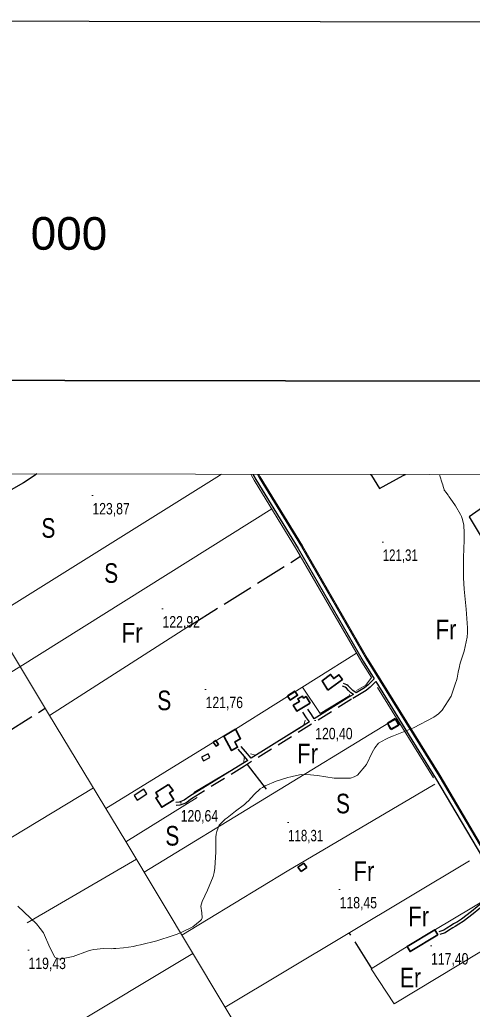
# Model space of a CAD drawing. Extents: x 487425 to 492029, y 4383576 to 4386788.
# Drawn here: x 488084 to 488430, y 4386031 to 4386788 of the extents above; entities that cross this region are included whole.
import ezdxf
from ezdxf.enums import TextEntityAlignment as Align

# ---------------------------------------------------------------- set-up
doc = ezdxf.new("R2010")
doc.units = 0
doc.header["$LTSCALE"] = 4
for name, pattern in [('DOTTED', [1.5, 0.3, -1.2]), ('LONG_DASHED', [7.5, 6, -1.5]), ('MEDIUM_DASHED', [4.5, 3, -1.5])]:
    doc.linetypes.add(name, pattern=pattern)
for name, color, linetype, lineweight in [('1', 7, 'Continuous', 13), ('2', 7, 'DOTTED', 13), ('21', 7, 'Continuous', 25), ('25', 7, 'LONG_DASHED', 25), ('38', 7, 'Continuous', 25), ('47', 7, 'Continuous', 35), ('48', 7, 'MEDIUM_DASHED', 25), ('49', 7, 'LONG_DASHED', 35), ('51', 7, 'Continuous', 13), ('7', 7, 'Continuous', 13), ('8', 7, 'Continuous', 25), ('9', 7, 'Continuous', 13)]:
    doc.layers.add(name, color=color, linetype=linetype, lineweight=lineweight)
doc.layers.add('31', color=7, linetype='Continuous')

msp = doc.modelspace()

# ---------------------------------------------------------------- linework, layer by layer
at = {"layer": '1', "lineweight": 25}
msp.add_lwpolyline([(487429.26, 4386787.97), (492029.26, 4386781.28), (492024.61, 4383576.28), (487424.61, 4383582.97)], close=True, dxfattribs=at)
at = {"layer": '1', "lineweight": 35}
msp.add_lwpolyline([(487611.46, 4386512.7), (491328.86, 4386507.3), (491325.3, 4384052.3), (487607.9, 4384057.7)], close=True, dxfattribs=at)
at = {"layer": '1'}
msp.add_lwpolyline([(487681.9, 4386441.2), (491258.2, 4386436), (491255.4, 4384123.8), (487678, 4384129)], close=True, dxfattribs=at)
at = {"layer": '21'}
for points in [[(488224.69, 4386221.07), (488229.62, 4386223.59), (488228.13, 4386226.51), (488223.2, 4386223.99)], [(488179.06, 4386199.54), (488171.66, 4386194.75), (488174.01, 4386191.12), (488181.41, 4386195.91)]]:
    msp.add_lwpolyline(points, close=True, dxfattribs=at)
at = {"layer": '25'}
for p, q in [((488352.62, 4386440.22), (488353.21, 4386439.31)), ((488377.66, 4386439.27), (488379.37, 4386440.19)), ((488215.18, 4386325.09), (488299, 4386377.62)), ((488257.98, 4386218.31), (488276.07, 4386195)), ((488353.54, 4386062.4), (488336.27, 4386089.61))]:
    msp.add_line(p, q, dxfattribs=at)
for points in [[(488353.21, 4386439.31), (488359.47, 4386429.53), (488377.66, 4386439.27)], [(488468.34, 4386435.15), (488427.95, 4386407.89), (488537.35, 4386226.21)], [(487959.27, 4386169.33), (487996.84, 4386194.26), (488103.35, 4386261.37)]]:
    msp.add_lwpolyline(points, dxfattribs=at)
at = {"layer": '38'}
for p, q in [((488262.43, 4386440.36), (488262.96, 4386439.44)), ((488265.95, 4386440.35), (488266.47, 4386439.44)), ((488305.7, 4386250.92), (488261.21, 4386223.13))]:
    msp.add_line(p, q, dxfattribs=at)
for points in [[(488262.96, 4386439.44), (488264.69, 4386436.44), (488297.09, 4386383.48), (488346.91, 4386297.31), (488355.27, 4386283.84)], [(488266.47, 4386439.44), (488267.3, 4386437.99), (488299.7, 4386385.03), (488349.51, 4386298.86), (488404.98, 4386209.41), (488439.82, 4386150.66)], [(488341.62, 4386273.2), (488338.88, 4386274.89), (488337.32, 4386276.62), (488335.55, 4386278.44), (488334.3, 4386279.37), (488331.97, 4386280.42)], [(488355.27, 4386283.84), (488350.65, 4386279.18), (488347.88, 4386276.91), (488341.62, 4386273.2)], [(488356.55, 4386281.75), (488402.39, 4386207.84), (488453.88, 4386121.01)], [(488339.39, 4386271.89), (488336.63, 4386270.25), (488309.43, 4386253.26)], [(488305.7, 4386250.92), (488303.56, 4386254.08), (488300.82, 4386258.33)], [(488261.21, 4386223.13), (488256.95, 4386228.17), (488253.45, 4386232.12)], [(488258.59, 4386221.5), (488254.78, 4386219.11), (488214.1, 4386194.12), (488209.88, 4386190.94), (488206.12, 4386189.52), (488203.42, 4386189.27)], [(488453.88, 4386121.01), (488448.21, 4386118.36), (488438.52, 4386113.1), (488429.84, 4386105.88), (488422.24, 4386099.99), (488419.03, 4386098.03), (488416.16, 4386096.34), (488414.35, 4386095.24), (488411.01, 4386093.24), (488408.74, 4386091.66), (488404.86, 4386090.4)]]:
    msp.add_lwpolyline(points, dxfattribs=at)
at = {"layer": '38', "linetype": 'MEDIUM_DASHED'}
for points in [[(488356.55, 4386281.75), (488352.25, 4386277.42), (488349.26, 4386274.95), (488337.87, 4386268.21), (488256.04, 4386217.09), (488215.44, 4386192.14), (488211.04, 4386188.83), (488206.66, 4386187.18), (488203.64, 4386186.89)], [(488339.39, 4386271.89), (488337.4, 4386273.11), (488335.65, 4386275.06), (488334.04, 4386276.71), (488333.13, 4386277.39), (488331.03, 4386278.33)], [(488309.43, 4386253.26), (488307.23, 4386256.51), (488304.51, 4386260.71)], [(488258.59, 4386221.5), (488254.64, 4386226.17), (488251.16, 4386230.09)], [(488455.03, 4386119.07), (488449.22, 4386116.35), (488439.79, 4386111.23), (488431.25, 4386104.12), (488423.52, 4386098.14), (488420.19, 4386096.1), (488417.32, 4386094.41), (488415.51, 4386093.31), (488412.23, 4386091.34), (488409.75, 4386089.62), (488405.56, 4386088.26)]]:
    msp.add_lwpolyline(points, dxfattribs=at)
at = {"layer": '47'}
for points in [[(488319.98, 4386275.28), (488331.03, 4386283.48), (488328.39, 4386287.03), (488324.34, 4386284.03), (488321.98, 4386287.2), (488315.45, 4386282.34)], [(488288.95, 4386270.76), (488294.59, 4386274.49), (488296.68, 4386271.34), (488291.04, 4386267.61)], [(488306.37, 4386265.31), (488296.02, 4386259.2), (488293.39, 4386263.65), (488298.13, 4386266.45), (488296.85, 4386268.6), (488300.37, 4386270.69), (488301.27, 4386269.16), (488303.27, 4386270.35)], [(488240.14, 4386240.1), (488246.16, 4386229.01), (488250.82, 4386231.55), (488248.59, 4386235.62), (488253.02, 4386238.05), (488249.07, 4386245.24)], [(488232.2, 4386235.39), (488234.37, 4386232.36), (488236.24, 4386233.7), (488234.07, 4386236.73)], [(488198, 4386203.15), (488188.1, 4386196.88), (488189.97, 4386193.91), (488188.15, 4386192.76), (488192.67, 4386185.59), (488201.86, 4386191.39), (488198.57, 4386196.58), (488201.34, 4386198.35)], [(488380.55, 4386079.09), (488401.74, 4386091.88), (488404.05, 4386088.05), (488382.86, 4386075.26)]]:
    msp.add_lwpolyline(points, close=True, dxfattribs=at)
at = {"layer": '48'}
msp.add_lwpolyline([(488365.61, 4386249.7), (488372.39, 4386253.28), (488374.68, 4386248.93), (488367.9, 4386245.35)], close=True, dxfattribs=at)
at = {"layer": '49'}
for points in [[(488365.46, 4386249.93), (488371.42, 4386253.4), (488374.29, 4386248.48), (488368.33, 4386245.01)], [(488303.73, 4386139.45), (488299.34, 4386136.39), (488296.99, 4386139.75), (488301.38, 4386142.81)]]:
    msp.add_lwpolyline(points, close=True, dxfattribs=at)
at = {"layer": '51'}
for p, q in [((488066.84, 4386333.15), (488236.98, 4386439.48)), ((488236.98, 4386439.48), (488238.44, 4386440.39)), ((488260.97, 4386440.36), (488261.49, 4386439.45)), ((488267.01, 4386440.35), (488267.53, 4386439.44)), ((488106.67, 4386255.89), (488215.52, 4386325.31)), ((488249.07, 4386245.24), (488341.86, 4386303.49)), ((488357.86, 4386277.23), (488400.78, 4386208.01)), ((488179.28, 4386135.96), (488366.63, 4386250.24)), ((488149.84, 4386184.74), (488240.22, 4386240.15)), ((488140.34, 4386200.41), (487948.07, 4386084.44)), ((488165.31, 4386159.25), (488219.72, 4386193.22)), ((488173.29, 4386145.95), (488089.59, 4386097.17)), ((488241.28, 4386032.7), (488428.26, 4386144.71)), ((488445.81, 4386118.1), (488401.07, 4386091.47)), ((488216.53, 4386073.86), (488008.28, 4385949.02))]:
    msp.add_line(p, q, dxfattribs=at)
for points in [[(488261.49, 4386439.45), (488263.59, 4386435.79), (488295.99, 4386382.82), (488345.81, 4386296.64), (488353.17, 4386284.79)], [(488267.53, 4386439.44), (488268.09, 4386438.46), (488300.49, 4386385.5), (488350.29, 4386299.34), (488405.77, 4386209.89), (488439.12, 4386153.67)], [(488276.91, 4386414.02), (488084.14, 4386293.16), (487939.73, 4386205.49), (487959.27, 4386169.33)], [(488065.17, 4386324.54), (488105.89, 4386257.16), (488165.17, 4386159.48), (488216.27, 4386074.28), (488260.52, 4386000.7), (488321.21, 4385902.03)], [(488341.89, 4386275.03), (488348.98, 4386279), (488353.17, 4386284.79)], [(488300.57, 4386277.57), (488314.08, 4386257.27), (488336.74, 4386271.11), (488336.45, 4386271.94)], [(488260.69, 4386226.59), (488264.58, 4386225.57), (488300.61, 4386247.67), (488301.45, 4386248.71), (488301.99, 4386250.2), (488302.54, 4386252.15)], [(488217.29, 4386196.85), (488255.43, 4386219.6), (488255.93, 4386223.72)], [(488401.84, 4386203.3), (488288.78, 4386136.85), (488208.12, 4386087.87)], [(488380.55, 4386079.09), (488353.12, 4386062.14), (488370.52, 4386035.39), (488468.26, 4386094.08)]]:
    msp.add_lwpolyline(points, dxfattribs=at)
at = {"layer": '7'}
for p, q in [((488139.1, 4386424), (488140.1, 4386424)), ((488361.36, 4386388.46), (488362.36, 4386388.46)), ((488192.8, 4386337.49), (488193.8, 4386337.49)), ((488225.79, 4386275.82), (488226.79, 4386275.82)), ((488309.69, 4386251.99), (488310.69, 4386251.99)), ((488206.72, 4386189.09), (488207.72, 4386189.09)), ((488289, 4386173.97), (488290, 4386173.97)), ((488328.4, 4386122.66), (488329.4, 4386122.66)), ((488090.2, 4386076.23), (488091.2, 4386076.23)), ((488398.36, 4386079.7), (488399.36, 4386079.7))]:
    msp.add_line(p, q, dxfattribs=at)
at = {"layer": '8'}
msp.add_line((488097.04, 4386440.6), (488095.68, 4386439.69), dxfattribs=at)
msp.add_lwpolyline([(488095.68, 4386439.69), (488086.98, 4386433.88), (488068.27, 4386423.32), (488063.87, 4386421.53), (488059.81, 4386420.22), (488047.97, 4386419.6), (488040.04, 4386422.79), (488038.44, 4386423.88), (488037.1, 4386425.08), (488034.42, 4386430.16), (488033.19, 4386435.13), (488032.76, 4386436.26), (488032.3, 4386437.27), (488030.47, 4386439.79)], dxfattribs=at)
at = {"layer": '9'}
msp.add_line((488405.27, 4386440.15), (488405.57, 4386439.23), dxfattribs=at)
for points in [[(488405.57, 4386439.23), (488407.38, 4386433.64), (488407.85, 4386432.15), (488408.23, 4386430.92), (488408.83, 4386428.75), (488409.02, 4386428.19), (488409.15, 4386427.97), (488409.31, 4386427.74), (488410.13, 4386426.69), (488411.88, 4386424.33), (488412.62, 4386423.27), (488413.47, 4386422.04), (488417.49, 4386416.1), (488421.39, 4386409.58), (488422.17, 4386407.97), (488422.82, 4386406.45), (488424.07, 4386401.69), (488424.27, 4386395.28), (488424.26, 4386392.73), (488424.21, 4386389.83), (488423.81, 4386376.57), (488423.73, 4386361.1), (488423.9, 4386356.82), (488424.15, 4386352.55), (488425.72, 4386337.12), (488426.77, 4386322.82), (488426.68, 4386319.25), (488426.44, 4386315.86), (488424.19, 4386305.02), (488421.5, 4386296.65), (488420.97, 4386294.81), (488420.54, 4386293.18), (488419.75, 4386289), (488418.81, 4386284.46), (488418.28, 4386282.59), (488417.63, 4386280.46), (488414.3, 4386270.57), (488407.38, 4386259.82), (488404.47, 4386257.15), (488401.12, 4386254.6), (488385.44, 4386246.51), (488370.08, 4386240.31), (488366.93, 4386238.95), (488364.27, 4386237.75), (488358.68, 4386234.74), (488355.76, 4386231.03), (488354.79, 4386229.39), (488353.75, 4386227.49), (488349.39, 4386218.4), (488342.67, 4386210.2), (488340.14, 4386208.87), (488337.32, 4386207.93), (488324.71, 4386207.92), (488312.03, 4386209.91), (488309.16, 4386210.25), (488306.58, 4386210.49), (488299.56, 4386210.57), (488293.46, 4386209.48), (488291.46, 4386208.98), (488289.31, 4386208.39), (488280.42, 4386205.55), (488271.84, 4386201.92), (488269.9, 4386200.83), (488268.15, 4386199.71), (488263.37, 4386195.35), (488259.03, 4386190.59), (488257.56, 4386189.22), (488255.96, 4386187.82), (488249.21, 4386182.57), (488242.69, 4386177.65), (488241.24, 4386176.47), (488239.95, 4386175.37), (488236.58, 4386172.02), (488234.77, 4386167.15), (488234.47, 4386165.08), (488234.24, 4386162.71), (488234.14, 4386151.53), (488233.41, 4386139), (488232.79, 4386135.77), (488232, 4386132.64), (488227.65, 4386122.19), (488223.64, 4386113.6), (488223.06, 4386111.64), (488222.72, 4386109.86), (488223.42, 4386104.94), (488223.69, 4386101.03), (488223.07, 4386099.89), (488222.16, 4386098.71), (488216.38, 4386094.25), (488207.45, 4386089.79), (488204.55, 4386088.62), (488201.47, 4386087.47), (488188.82, 4386083.57), (488176.51, 4386080.44), (488173.65, 4386079.79), (488171.02, 4386079.23)], [(488171.02, 4386079.23), (488163.48, 4386077.98), (488157.46, 4386077.52), (488155.79, 4386077.47), (488154.12, 4386077.44), (488148.07, 4386077.59), (488140.82, 4386076.87), (488138.38, 4386076.29), (488135.77, 4386075.56), (488124.79, 4386071.53), (488114.64, 4386069.48), (488112.55, 4386069.98), (488110.78, 4386070.95), (488106.96, 4386078.33), (488102.12, 4386089.53), (488099.7, 4386092.9), (488096.81, 4386096.39), (488082.45, 4386110.01)]]:
    msp.add_lwpolyline(points, dxfattribs=at)

# ---------------------------------------------------------------- texts
at = {"layer": '2', "width": 1.05}
msp.add_text('000', height=25, rotation=359.917, dxfattribs=at).set_placement((488092.36, 4386612.09))
at = {"layer": '31'}
for s, width, p in [('S', 0.8, (488105.93, 4386391.79)), ('S', 0.8, (488153.99, 4386357.27)), ('Fr', 0.85, (488170.01, 4386311.65)), ('Fr', 0.85, (488410.31, 4386314.12)), ('S', 0.8, (488194.66, 4386259.87)), ('Fr', 0.85, (488304.33, 4386219.19)), ('S', 0.8, (488331.45, 4386180.97)), ('S', 0.8, (488200.83, 4386156.31)), ('Fr', 0.85, (488347.46, 4386129.19)), ('Fr', 0.85, (488389.36, 4386094.67)), ('Er', 0.8, (488383.21, 4386047.82))]:
    msp.add_text(s, height=15, dxfattribs=dict(at, width=width)).set_placement(p, align=Align.CENTER)
at = {"layer": '7'}
for s, width, p in [('123,87', 0.8, (488139.6, 4386409.63)), ('121,31', 0.75, (488361.86, 4386374.09)), ('122,92', 0.8, (488193.3, 4386323.12)), ('121,76', 0.8, (488226.29, 4386261.45)), ('120,40', 0.8, (488310.19, 4386237.62)), ('120,64', 0.8, (488207.22, 4386174.72)), ('118,31', 0.75, (488289.5, 4386159.6)), ('118,45', 0.8, (488328.9, 4386108.29)), ('119,43', 0.8, (488090.7, 4386061.86)), ('117,40', 0.8, (488398.86, 4386065.33))]:
    msp.add_text(s, height=8.75, dxfattribs=dict(at, width=width)).set_placement(p)

doc.saveas('drawing.dxf')
